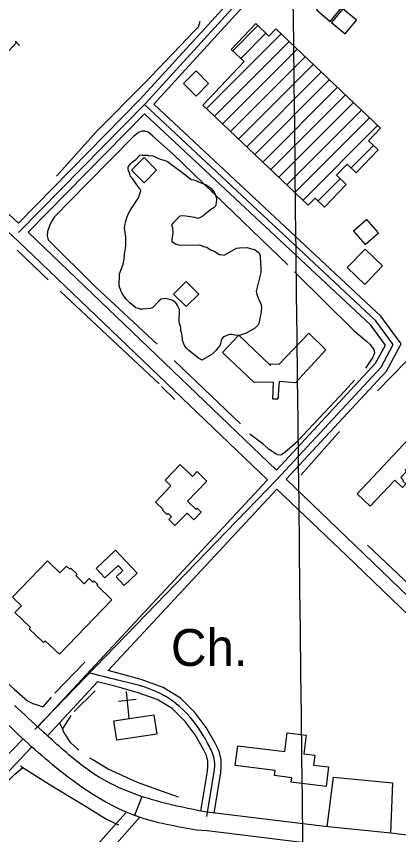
# Model space of a CAD drawing. Extents: x 3683613 to 3738215, y 469626 to 495384.
# Drawn here: x 3697680 to 3698541, y 483982 to 485823 of the extents above; entities that cross this region are included whole.
import ezdxf

# ---------------------------------------------------------------- set-up
doc = ezdxf.new("R2010")
doc.units = 0
for name, color, linetype in [('V-BLDG-OTLN', 7, 'Continuous'), ('V-GRID-MAJR', 7, 'Continuous'), ('V-ROAD-CNTR', 7, 'Continuous'), ('V-SITE-OTLN', 7, 'Continuous'), ('V-SITE-OTLN-IDEN', 7, 'Continuous'), ('V-SITE-VEGE', 7, 'Continuous'), ('V-TOPO-SHOR', 7, 'Continuous'), ('V-UTIL-LINE', 7, 'Continuous')]:
    doc.layers.add(name, color=color, linetype=linetype)

msp = doc.modelspace()

# ---------------------------------------------------------------- linework, layer by layer
at = {"layer": 'V-BLDG-OTLN'}
for p, q in [((3698167.6227591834, 485745.932936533), (3698224.2076657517, 485802.5178431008)), ((3698108.4749390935, 485616.0744383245), (3698276.5446132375, 485784.14411246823)), ((3698185.749381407, 485728.7042196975), (3698242.3339883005, 485785.2888265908)), ((3698126.6012967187, 485598.8454568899), (3698294.670933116, 485766.9150932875)), ((3698144.727654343, 485581.6164754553), (3698312.7972529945, 485749.6860741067)), ((3698162.8540119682, 485564.3874940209), (3698330.923572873, 485732.4570549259)), ((3698180.9803695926, 485547.1585125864), (3698349.049892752, 485715.2280357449)), ((3698199.106727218, 485529.9295311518), (3698367.1762126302, 485697.99901656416)), ((3698217.2330848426, 485512.7005497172), (3698385.302532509, 485680.76999738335)), ((3698235.359442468, 485495.47156828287), (3698403.4288523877, 485663.5409782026)), ((3698253.485800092, 485478.24258684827), (3698421.555172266, 485646.31195902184)), ((3698271.612157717, 485461.01360541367), (3698439.6814921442, 485629.0829398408)), ((3698289.7385153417, 485443.7846239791), (3698457.807812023, 485611.85392066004)), ((3698307.864872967, 485426.55564254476), (3698475.9341319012, 485594.6249014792)), ((3698325.9912305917, 485409.32666111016), (3698494.06045178, 485577.3958822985)), ((3698434.0642575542, 485482.0443490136), (3698484.678751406, 485532.65884286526)), ((3698359.685064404, 485407.6651558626), (3698409.5974009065, 485457.57749236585))]:
    msp.add_line(p, q, dxfattribs=at)
for points in [[(3698382.367510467, 485868.192098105), (3698356.6395104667, 485837.56409810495), (3698387.2665104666, 485811.83609810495), (3698412.995510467, 485842.463098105)], [(3698415.8195730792, 485840.3153792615), (3698390.091573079, 485809.6873792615), (3698420.718573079, 485783.9593792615), (3698446.4475730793, 485814.5863792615)], [(3698264.6720000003, 485795.429), (3698500.417, 485571.354), (3698473.625, 485543.16500000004), (3698495.002, 485522.847), (3698445.703, 485470.981), (3698425.071, 485490.593), (3698401.24, 485465.521), (3698422.886, 485444.947), (3698374.272, 485393.8), (3698352.971, 485414.047), (3698337.81, 485398.093), (3698100.4280000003, 485623.723), (3698193.348, 485721.482), (3698164.52, 485748.882), (3698219.632, 485806.867), (3698249.004, 485778.949)], [(3698085.0490957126, 485643.9803449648), (3698113.395095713, 485672.2023449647), (3698085.173095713, 485700.54834496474), (3698056.8270957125, 485672.32634496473)], [(3697967.9668765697, 485448.8433130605), (3697996.31287657, 485477.06531306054), (3697968.09087657, 485505.41131306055), (3697939.7448765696, 485477.18931306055)], [(3698469.6240000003, 485366.228), (3698439.39, 485340.038), (3698465.58, 485309.804), (3698495.8140000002, 485335.994)], [(3698464.8340000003, 485219.755), (3698425.39, 485257.71400000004), (3698465.795, 485299.699), (3698505.239, 485261.74)], [(3698062.747720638, 485170.07612462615), (3698091.0937206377, 485198.29812462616), (3698062.8717206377, 485226.6441246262), (3698034.5257206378, 485198.4221246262)], [(3698144.591, 485067.087), (3698181.123, 485105.585), (3698252.5500000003, 485037.80700000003), (3698252.083, 485041.081), (3698272.579, 485040.856), (3698339.325, 485110.115), (3698377.097, 485072.586), (3698308.679, 484998.86), (3698272.593, 485001.846), (3698268.915, 484962.047), (3698258.057, 484961.66000000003), (3698259.7770000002, 485000.197), (3698215.765, 484999.548)], [(3698447.681, 484748.985), (3698575.286, 484884.712), (3698577.055, 484883.049), (3698587.795, 484894.471), (3698615.975, 484867.976), (3698614.531, 484866.44), (3698621.3880000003, 484859.99100000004), (3698611.56, 484849.538), (3698605.873, 484854.885), (3698555.8910000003, 484801.721), (3698558.896, 484798.89900000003), (3698546.046, 484785.231), (3698552.602, 484779.07), (3698551.0870000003, 484777.45900000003), (3698557.88, 484771.071), (3698550.114, 484762.809), (3698532.382, 484779.478), (3698477.4220000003, 484721.02)], [(3698015.254, 484779.482), (3698049.603, 484814.742), (3698076.989, 484788.063), (3698087.5870000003, 484798.94), (3698109.718, 484777.381), (3698065.987, 484732.493), (3698085.115, 484713.854), (3698087.796, 484716.604), (3698096.9220000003, 484707.712), (3698080.235, 484690.58), (3698064.8540000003, 484705.566), (3698037.569, 484677.55700000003), (3698023.815, 484690.957), (3698029.662, 484696.96), (3698022.285, 484704.146), (3698020.091, 484701.898), (3698009.839, 484711.886), (3698011.056, 484713.135), (3697993.426, 484730.31200000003), (3698028.631, 484766.447)], [(3697952.725, 484569.868), (3697903.813, 484621.701), (3697860.228, 484580.572), (3697879.9, 484559.726), (3697909.454, 484587.61600000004), (3697920.096, 484576.33900000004), (3697904.7830000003, 484561.88800000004), (3697923.383, 484542.178)], [(3697895.557, 484510.53500000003), (3697777.166, 484387.765), (3697745.612, 484418.19), (3697741.526, 484413.95300000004), (3697709.465, 484444.87), (3697712.289, 484447.798), (3697677.117, 484481.721), (3697691.68, 484496.827), (3697671.847, 484515.954), (3697750.62, 484597.636), (3697778.257, 484570.983), (3697793.025, 484586.3), (3697800.589, 484579.005), (3697803.214, 484581.727), (3697817.188, 484568.253), (3697814.089, 484565.036), (3697833.4020000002, 484546.416), (3697844.443, 484557.86600000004), (3697852.2800000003, 484550.305), (3697855.045, 484553.174), (3697863.12, 484545.38300000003), (3697861.336, 484543.534)], [(3698179.088, 484181.917), (3698285.1780000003, 484168.732), (3698290.429, 484210.994), (3698333.319, 484205.663), (3698328.143, 484164.01300000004), (3698352.713, 484160.95900000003), (3698349.916, 484138.456), (3698383.531, 484134.28), (3698378.0470000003, 484090.16000000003), (3698299.3910000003, 484099.935), (3698300.628, 484109.893), (3698261.845, 484114.71400000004), (3698263.244, 484125.957), (3698173.519, 484137.108)]]:
    msp.add_lwpolyline(points, close=True, dxfattribs=at)
at = {"layer": 'V-GRID-MAJR'}
msp.add_spline([(3698426.819, 475163.32300000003), (3698357.213, 481220.729), (3698287.573, 487281.219), (3698217.932, 493341.72000000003), (3698217.897, 493344.793)], degree=3, dxfattribs=at)
at = {"layer": 'V-ROAD-CNTR'}
msp.add_line((3697946.4740681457, 484024.4849249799), (3697963.5780339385, 484067.80883833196), dxfattribs=at)
for points in [[(3697684.823591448, 485357.82625829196), (3697959.504042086, 485636.62570069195), (3698207.8535453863, 485909.039155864)], [(3697685.2705905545, 485336.9073001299), (3697970.393020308, 485626.30572133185), (3698229.0045030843, 485909.9741539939)], [(3697113.3937343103, 485890.27519339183), (3697684.823591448, 485357.82625829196)], [(3697989.97198115, 485625.51772290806), (3698229.5345020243, 485888.2911973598)], [(3698490.0989808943, 485138.3056973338), (3697969.080022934, 485624.49672494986)], [(3698287.7483855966, 484781.52641089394), (3698514.143932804, 485024.8229243), (3698546.9608671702, 485086.0268018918), (3698501.366958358, 485148.30767733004), (3697989.97198115, 485625.51772290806)], [(3697376.924207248, 485603.71676651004), (3697684.2315926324, 485317.3733391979), (3698245.63146983, 484780.3034133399)], [(3697706.755547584, 485337.3422992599), (3697969.2740225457, 485603.798766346)], [(3698266.0694289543, 484802.26736941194), (3698489.5379820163, 485042.41888910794), (3698511.5929379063, 485083.550806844), (3698478.8310034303, 485128.30371733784), (3697969.2740225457, 485603.798766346)], [(3697706.755547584, 485337.3422992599), (3698266.0694289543, 484802.26736941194)], [(3698501.84095741, 485033.62090670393), (3698529.2769025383, 485084.78880436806), (3698490.0989808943, 485138.3056973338)], [(3697721.938517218, 484218.69553655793), (3698266.6904277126, 484780.9154121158), (3698501.84095741, 485033.62090670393), (3698501.84095741, 485033.62090670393), (3698501.84095741, 485033.62090670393)], [(3697728.395504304, 484224.4535250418), (3698245.63146983, 484780.3034133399)], [(3698287.7483855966, 484781.52641089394), (3698443.757073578, 484632.27970938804), (3698842.7733361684, 484248.4078130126)], [(3697887.3601863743, 484351.2492714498), (3698267.31142647, 484759.5634548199)], [(3698267.31142647, 484759.5634548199), (3698422.9891151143, 484610.6317526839), (3699154.2846525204, 483907.0911597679)], [(3698125.840709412, 484030.516912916), (3698141.1446788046, 484121.6817305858), (3698141.3276784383, 484135.705702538), (3698141.5176780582, 484150.37267320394), (3698137.0246870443, 484169.9906339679), (3698128.3177044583, 484187.4015991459), (3698107.968745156, 484222.94952804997), (3698082.89179531, 484256.19646155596), (3698075.7098096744, 484263.4154471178), (3698050.098860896, 484289.15839563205), (3698010.824939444, 484313.133347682), (3697961.564037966, 484330.585312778), (3697887.3601863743, 484351.2492714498)], [(3697750.529460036, 484204.2025655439), (3697863.3312344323, 484325.42432309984)], [(3698096.06676896, 484034.36290522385), (3698111.17673874, 484124.3757251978), (3698111.329738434, 484136.09570175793), (3698111.473738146, 484147.1726796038), (3698108.5847439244, 484159.788654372), (3698101.8637573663, 484173.2296274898), (3698082.8747953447, 484206.3995611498), (3698060.1778407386, 484236.4925009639), (3698054.44185221, 484242.25748943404), (3698031.380898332, 484265.4364430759), (3697997.860965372, 484285.89940214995), (3697952.520056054, 484301.9613700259), (3697905.2021506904, 484315.1393436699), (3697863.3312344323, 484325.42432309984)], [(3696977.3860063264, 483379.3632152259), (3696892.0311770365, 483294.0663858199), (3696669.808621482, 483059.074855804), (3696649.3916623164, 483042.13388968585), (3696617.86972536, 483064.73584448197), (3697149.5006620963, 483632.7797083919), (3697161.94363721, 483645.43668307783), (3697693.874573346, 484195.82358230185)], [(3697763.061434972, 483856.064261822), (3697728.659503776, 483822.66132862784), (3697545.348870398, 484000.0179739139), (3697714.915531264, 484179.170615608)], [(3698109.2657425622, 484022.38292918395), (3698126.1607087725, 484123.0287278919)], [(3698380.494200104, 483999.53497488), (3698394.795171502, 484111.4227511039), (3698527.199906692, 484098.518776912), (3698522.8349154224, 483985.05800383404)], [(3697926.6361078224, 484030.73391248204), (3697818.2363246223, 483909.63715467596), (3697763.0604349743, 483856.0632618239)], [(3697903.1541547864, 483842.83528828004), (3697848.53726402, 483897.7471784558), (3697958.2960445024, 484021.04793185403)], [(3701641.2606785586, 483606.69876055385), (3699984.6349918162, 483805.4213631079), (3699008.2059446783, 483924.977123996), (3698523.9459132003, 483984.94500406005), (3698374.8092114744, 484000.1129737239), (3698104.1967527, 484033.15990763)], [(3699965.6370298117, 483762.896448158), (3699081.3637983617, 483872.34722925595), (3698506.56594796, 483941.433091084), (3698110.359740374, 483990.68399258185), (3698086.4407882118, 483992.10698973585)]]:
    msp.add_lwpolyline(points, dxfattribs=at)
for points in [[(3698126.1607087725, 484123.0287278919), (3698126.4957081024, 484148.772676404), (3698115.0907309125, 484180.315613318), (3698071.5348180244, 484246.3444812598), (3698004.342952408, 484299.51637491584), (3697909.0041430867, 484329.651314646), (3697844.7432716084, 484345.438283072)], [(3698104.1967527, 484033.15990763), (3698004.638951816, 484055.2038635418), (3697867.9022252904, 484110.5707528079), (3697776.681407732, 484180.63461267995), (3697738.4874841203, 484215.18554357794), (3697676.009609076, 484272.73742847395)], [(3698086.4407882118, 483992.10698973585), (3697951.776057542, 484023.1799275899), (3697828.1923047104, 484088.45779703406), (3697699.4655621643, 484193.6365866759), (3697640.4476802, 484249.30647533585)]]:
    msp.add_spline(points, degree=3, dxfattribs=at)
at = {"layer": 'V-SITE-OTLN'}
for p, q in [((3697934.42, 484243.91433582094), (3697928.45, 484303.61633582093)), ((3697950.341, 484285.7053358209), (3697910.54, 484281.7263358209))]:
    msp.add_line(p, q, dxfattribs=at)
msp.add_lwpolyline([(3697996.43, 484207.635), (3697906.574, 484194.20300000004), (3697900.051, 484237.84), (3697989.907, 484251.272)], close=True, dxfattribs=at)
at = {"layer": 'V-SITE-VEGE'}
for points in [[(3698221.981, 485197.20900000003), (3698224.332, 485191.613), (3698231.4080000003, 485173.702), (3698232.596, 485170.341), (3698231.685, 485157.924), (3698230.613, 485154.52400000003), (3698226.501, 485131.906), (3698224.326, 485127.359), (3698216.556, 485120.462), (3698197.575, 485109.984), (3698186.366, 485106.406), (3698181.877, 485105.2), (3698171.715, 485106.15), (3698164.934, 485107.16000000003), (3698160.426, 485107.082), (3698146.983, 485102.33900000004), (3698142.574, 485096.625), (3698141.505, 485093.223), (3698139.41, 485084.169), (3698133.913, 485076.184), (3698129.483, 485071.596), (3698120.626, 485062.423), (3698098.302, 485049.636), (3698096.029, 485050.721), (3698090.336, 485054.006), (3698068.61, 485071.662), (3698062.876, 485077.19800000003), (3698059.399, 485082.77400000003), (3698054.694, 485093.963), (3698054.6350000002, 485097.346), (3698053.291, 485109.72000000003), (3698050.938, 485115.31700000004), (3698050.801, 485123.204), (3698048.429, 485129.93), (3698047.184, 485136.67), (3698047.84, 485163.73600000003), (3698043.174, 485172.67100000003), (3698040.862, 485176.014), (3698039.697, 485178.246), (3698032.836, 485183.76300000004), (3698024.9080000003, 485185.881), (3698022.6350000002, 485186.966), (3698016.9820000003, 485187.99700000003), (3698012.473, 485187.917), (3698006.8570000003, 485186.69200000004), (3698001.3030000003, 485182.086), (3697988.0160000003, 485168.32800000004), (3697982.42, 485165.974), (3697965.537, 485164.553), (3697958.774, 485164.434), (3697956.501, 485165.52400000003), (3697949.699, 485167.66000000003), (3697935.98, 485178.693), (3697927.954, 485186.44200000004), (3697918.703, 485199.80700000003), (3697916.37, 485204.276), (3697911.648, 485216.59500000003), (3697911.5470000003, 485222.229), (3697912.401, 485238.025), (3697912.3030000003, 485243.659), (3697920.944, 485265.229), (3697923.002, 485276.538), (3697923.932, 485287.824), (3697925.949, 485301.38800000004), (3697926.9790000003, 485307.043), (3697926.762, 485319.439), (3697926.623, 485327.326), (3697924.036, 485346.444), (3697926.0530000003, 485360.006), (3697928.171, 485367.936), (3697932.5, 485378.153), (3697936.8710000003, 485386.12200000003), (3697942.347, 485395.23600000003), (3697951.147, 485407.79000000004), (3697955.536, 485414.63), (3697956.585, 485419.156), (3697960.896, 485430.504), (3697959.71, 485433.865), (3697957.416, 485436.081), (3697956.2490000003, 485438.315), (3697948.166, 485449.446), (3697942.392, 485457.237), (3697937.786, 485462.791), (3697936.6, 485466.15400000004), (3697931.878, 485478.473), (3697931.8000000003, 485482.978), (3697932.887, 485485.25200000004), (3697938.4050000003, 485492.112), (3697941.725, 485495.55100000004), (3697949.515, 485501.324), (3697958.373, 485510.495), (3697962.862, 485511.701), (3697965.133, 485510.614), (3697976.403, 485510.811), (3697978.677, 485509.721), (3697985.437, 485509.844), (3697989.965, 485508.793), (3697999.06, 485504.443), (3698002.481, 485502.248), (3698017.208, 485497.996), (3698020.609, 485496.927)], [(3698020.609, 485496.927), (3698061.727, 485466.082), (3698074.302, 485456.156), (3698079.954, 485455.12700000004), (3698086.756, 485452.99100000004), (3698089.029, 485451.90400000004), (3698109.47, 485443.243), (3698118.6040000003, 485436.63800000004), (3698123.21, 485431.082), (3698124.378, 485428.848), (3698127.855, 485423.275), (3698130.2290000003, 485416.55100000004), (3698131.453, 485410.936), (3698129.416, 485398.5), (3698128.347, 485395.101), (3698126.133, 485392.80700000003), (3698122.792, 485390.495), (3698120.538, 485390.456), (3698098.315, 485372.032), (3698089.359, 485368.49100000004), (3698082.557, 485370.62700000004), (3698056.558, 485374.684), (3698048.69, 485373.418), (3698033.17, 485358.495), (3698029.866, 485353.928), (3698032.238, 485347.204), (3698032.416, 485337.06), (3698030.4560000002, 485320.119), (3698030.5160000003, 485316.738), (3698038.503, 485311.24100000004), (3698047.578, 485308.02), (3698091.528, 485308.786), (3698099.453, 485306.67), (3698101.7290000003, 485305.583), (3698109.656, 485303.467), (3698117.642, 485297.966), (3698124.443, 485295.832), (3698138.1240000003, 485287.054), (3698140.376, 485287.093), (3698148.286, 485286.104), (3698153.881, 485288.45300000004), (3698170.6070000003, 485298.89400000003), (3698176.202, 485301.245), (3698182.944, 485302.49), (3698199.848, 485302.78500000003), (3698206.65, 485300.64900000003), (3698216.83, 485298.572), (3698227.109, 485290.862), (3698228.2770000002, 485288.62700000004), (3698229.483, 485284.14), (3698229.54, 485280.759), (3698231.08, 485257.115), (3698231.259, 485246.971), (3698222.813, 485214.131), (3698220.713, 485205.079), (3698221.981, 485197.20900000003)]]:
    msp.add_lwpolyline(points, dxfattribs=at)
at = {"layer": 'V-TOPO-SHOR'}
for p, q in [((3698033.166, 485513.22500000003), (3697987.696, 485553.49100000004)), ((3698171.092, 485380.191), (3698033.166, 485513.22500000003)), ((3698291.636, 485264.362), (3698171.092, 485380.191)), ((3697858.92, 485214.326), (3697751.85, 485320.523)), ((3697682.0300000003, 485297.106), (3697752.356, 485230.468)), ((3697778.839, 485204.938), (3698001.645, 484996.47000000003)), ((3697997.61, 485085.38800000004), (3697858.92, 485214.326)), ((3698185.4390000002, 484906.425), (3698035.947, 485049.114)), ((3698558.525, 485046.28500000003), (3698493.468, 484980.338)), ((3698007.177, 484990.004), (3698037.5160000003, 484960.982)), ((3698408.04, 484889.064), (3698321.8740000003, 484791.516)), ((3697834.235, 484370.15), (3697767.2490000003, 484300.271)), ((3697857.628, 484305.358), (3697810.288, 484259.251)), ((3697759.061, 484291.163), (3697739.9390000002, 484269.499)), ((3697803.3310000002, 484249.628), (3697784.647, 484220.239))]:
    msp.add_line(p, q, dxfattribs=at)
for points in [[(3697771.095, 485463.586), (3697860.759, 485564.173), (3697968.029, 485672.342), (3698081.699, 485790.946), (3698090.301, 485799.775), (3698094.219, 485812.628)], [(3697987.696, 485553.49100000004), (3697977.231, 485562.342), (3697969.569, 485564.968), (3697962.7660000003, 485564.605), (3697955.446, 485561.787), (3697943.85, 485552.919), (3697838.735, 485446.407), (3697765.627, 485371.094), (3697758.416, 485360.104), (3697754.714, 485351.61100000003), (3697750.787, 485339.303), (3697750.097, 485329.489), (3697751.85, 485320.523)], [(3698306.832, 485247.946), (3698440.6520000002, 485116.493), (3698469.296, 485092.351), (3698477.293, 485084.829), (3698485.335, 485073.765), (3698487.072, 485065.889), (3698483.384, 485056.306), (3698476.969, 485046.961), (3698466.815, 485031.849)], [(3698266.691, 484837.481), (3698276.235, 484836.787), (3698284.072, 484841.52), (3698313.426, 484867.235), (3698420.088, 484980.577), (3698441.836, 485004.83)], [(3698266.691, 484837.481), (3698249.666, 484848.15400000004), (3698236.432, 484860.239), (3698206.447, 484883)], [(3698471.022, 484633.572), (3698609.188, 484502.996), (3698667.931, 484447.376)], [(3697567.612, 484408.62200000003), (3697675.136, 484309.51300000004), (3697705.168, 484283.211), (3697717.778, 484277.112), (3697727.0840000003, 484273.69200000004), (3697739.9390000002, 484269.499)], [(3697820.858, 484172.076), (3697802.77, 484188.333), (3697787.203, 484212.37200000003), (3697784.647, 484220.239), (3697778.4930000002, 484232.689)], [(3698045.421, 484066.19800000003), (3698009.579, 484078.534), (3697952.923, 484099.313), (3697887.43, 484129.512), (3697864.92, 484142.83900000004), (3697853.937, 484149.505), (3697846.071, 484153.707)], [(3697573.674, 484020.086), (3697642.77, 484085.626), (3697676.881, 484117.945), (3697695.287, 484133.254)], [(3697689.919, 484136.70900000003), (3697695.287, 484133.254), (3697756.352, 484093.935), (3697830.215, 484049.608), (3697883.342, 484016.813), (3697910.683, 484003.995)]]:
    msp.add_lwpolyline(points, dxfattribs=at)
at = {"layer": 'V-UTIL-LINE'}
msp.add_line((3697680.369, 485764.142), (3697687.1210000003, 485757.564), dxfattribs=at)
msp.add_lwpolyline([(3697615.198, 485706.503), (3697618.687, 485703.835), (3697624.592, 485705.639), (3697636.286, 485717.642), (3697654.321, 485735.65400000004), (3697680.369, 485764.142), (3697677.326, 485766.89900000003)], dxfattribs=at)

# ---------------------------------------------------------------- texts
at = {"layer": 'V-SITE-OTLN-IDEN'}
msp.add_text('Ch.', height=82.99983200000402, dxfattribs=at).set_placement((3698028.460904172, 484361.4792509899))

doc.saveas('drawing.dxf')
